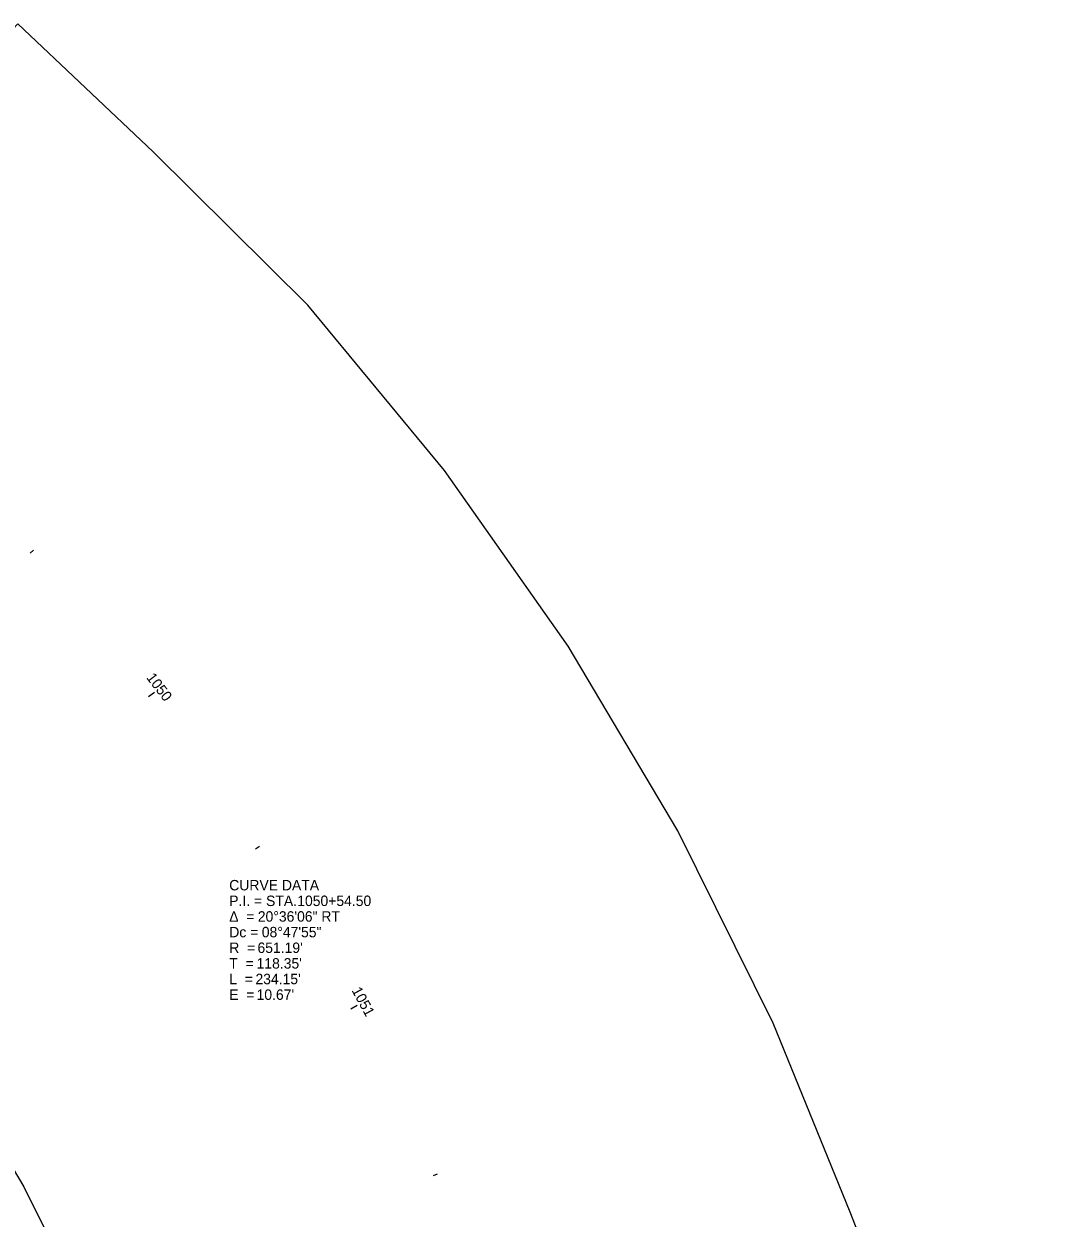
# Model space of a CAD drawing. Extents: x 1846275 to 1850613, y 577927 to 582526.
# Drawn here: x 1847530.8 to 1847804.3, y 581211.5 to 581532.2 of the extents above; entities that cross this region are included whole.
import ezdxf

# ---------------------------------------------------------------- set-up
doc = ezdxf.new("R2010")
doc.units = 0
for name, color, linetype in [('GE_P_Alignment_100_Cardinal_Points', 7, 'Continuous'), ('PM_P_Transverse_Line', 7, 'Continuous'), ('SH_Named_Boundary', 7, 'Continuous')]:
    doc.layers.add(name, color=color, linetype=linetype)

msp = doc.modelspace()

# ---------------------------------------------------------------- linework, layer by layer
at = {"layer": 'GE_P_Alignment_100_Cardinal_Points'}
for p, q in [((1847532.41, 581390.13), (1847533.31, 581390.93)), ((1847564.24, 581351.59), (1847565.83, 581352.8)), ((1847593.02, 581310.71), (1847594.02, 581311.37)), ((1847618.57, 581267.75), (1847620.33, 581268.71)), ((1847640.76, 581222.96), (1847641.85, 581223.45))]:
    msp.add_line(p, q, dxfattribs=at)
at = {"layer": 'SH_Named_Boundary'}
msp.add_lwpolyline([(1847529.1, 581532.22), (1847391.79, 581386.81), (1847428.14, 581352.48), (1847457.8, 581323.55), (1847484.74, 581290.92), (1847509.1, 581256.32), (1847530.73, 581219.96), (1847549.51, 581182.04), (1847566.47, 581140.21), (1847584.69, 581093.64), (1847606.16, 581040.65), (1847637.89, 580984.79), (1847804.3, 581095.73), (1847786.68, 581126.76), (1847770.94, 581166.52), (1847752.72, 581213.09), (1847732.01, 581263.86), (1847706.42, 581315.54), (1847676.94, 581365.1), (1847643.74, 581412.25), (1847607.02, 581456.71), (1847565.46, 581497.89)], close=True, dxfattribs=at)

# ---------------------------------------------------------------- texts
at = {"layer": 'GE_P_Alignment_100_Cardinal_Points'}
for s, rotation, p in [('1050', 307.3472, (1847563.52, 581356.65)), ('1051', 298.5485, (1847618.73, 581272.7))]:
    msp.add_text(s, height=2.8, rotation=rotation, dxfattribs=at).set_placement(p)
at = {"layer": 'PM_P_Transverse_Line'}
for s, p in [('CURVE DATA', (1847585.93, 581299.54)), ('P.I. = STA. ', (1847585.93, 581295.34)), ('1050+54.50', (1847604.19, 581295.34)), ('Δ  = ', (1847585.93, 581291.14)), ('20°36\'06" RT', (1847593.6, 581291.14)), ('Dc = ', (1847585.93, 581286.94)), ('08°47\'55"', (1847594.67, 581286.94)), ('R  = ', (1847585.93, 581282.74)), ("651.19'", (1847593.51, 581282.74)), ('T  = ', (1847585.93, 581278.54)), ("118.35'", (1847593.27, 581278.54)), ('L  = ', (1847585.93, 581274.34)), ("234.15'", (1847592.97, 581274.34)), ('E  = ', (1847585.93, 581270.14)), ("10.67'", (1847593.27, 581270.14))]:
    msp.add_text(s, height=2.8, dxfattribs=at).set_placement(p)

doc.saveas('drawing.dxf')
